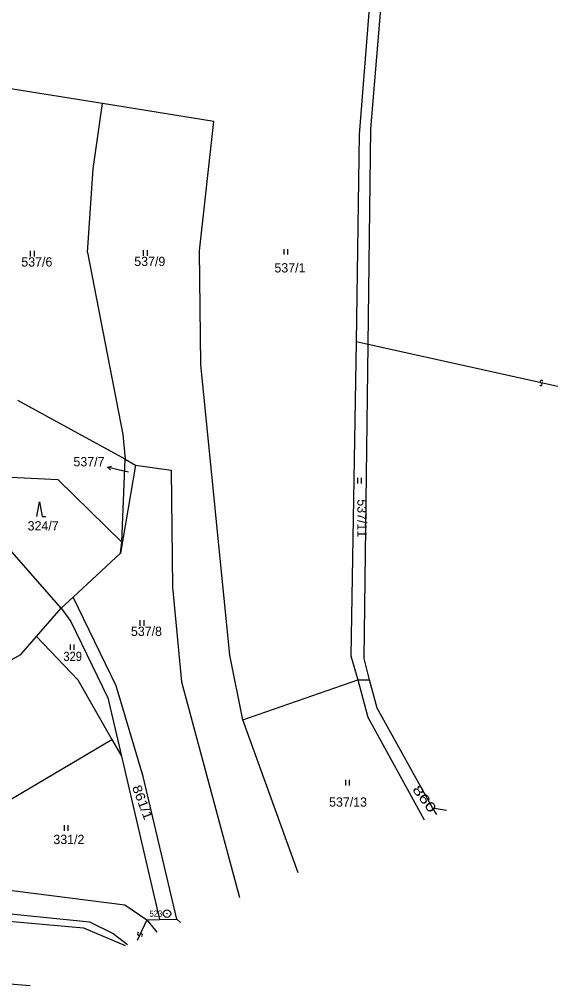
# Model space of a CAD drawing. Extents: x -680102 to -677253, y -1007548 to -1006096.
# Drawn here: x -679302.6 to -679159.4, y -1007457.9 to -1007197.5 of the extents above; entities that cross this region are included whole.
import ezdxf
from ezdxf.enums import TextEntityAlignment as Align

# ---------------------------------------------------------------- set-up
doc = ezdxf.new("R2010")
doc.units = 0
for name, color, linetype, lineweight in [('1', 7, 'Continuous', 25), ('16', 7, 'Continuous', 25), ('24', 7, 'Continuous', 25), ('25', 7, 'Continuous', 25), ('4', 7, 'Continuous', 25)]:
    doc.layers.add(name, color=color, linetype=linetype, lineweight=lineweight)
doc.layers.add('17', color=7, linetype='Continuous')
doc.layers.add('18', color=7, linetype='Continuous')

msp = doc.modelspace()

# ---------------------------------------------------------------- linework, layer by layer
at = {"layer": '1'}
for p, q in [((-679282.66, -1007237.83), (-679280.21, -1007220.22)), ((-679211, -1007228.57), (-679211.84, -1007284.41)), ((-679284.18, -1007260.33), (-679282.66, -1007237.83)), ((-679284.18, -1007260.33), (-679274.69, -1007309.38)), ((-679208.63, -1007285.12), (-679211.84, -1007284.41)), ((-679274.09, -1007316.01), (-679302.96, -1007300.22)), ((-679274.69, -1007309.38), (-679274.09, -1007316.01)), ((-679274.96, -1007338.38), (-679274.09, -1007316.01)), ((-679271.32, -1007317.64), (-679275.34, -1007341.36)), ((-679323.86, -1007319.92), (-679292.21, -1007321.54)), ((-679292.21, -1007321.54), (-679274.96, -1007338.38)), ((-679291.26, -1007356.13), (-679318.55, -1007325.27)), ((-679275.34, -1007341.36), (-679274.96, -1007338.38)), ((-679276.49, -1007377.07), (-679288.06, -1007353.16)), ((-679286.85, -1007375.44), (-679297.92, -1007363.78)), ((-679242.37, -1007386.23), (-679211.42, -1007375.5)), ((-679211.42, -1007375.5), (-679208.19, -1007375.44)), ((-679211.42, -1007375.5), (-679208.69, -1007385.51)), ((-679191.3, -1007409.95), (-679206.2, -1007383.07)), ((-679227.46, -1007427.46), (-679242.37, -1007386.23)), ((-679208.69, -1007385.51), (-679193.5, -1007413.16)), ((-679339.14, -1007427.85), (-679277.62, -1007391.57)), ((-679190.08, -1007411.72), (-679191.3, -1007409.95)), ((-679191.3, -1007409.95), (-679187.46, -1007410.62)), ((-679268.25, -1007440.13), (-679265.56, -1007443.49)), ((-679260.12, -1007439.93), (-679259.19, -1007440.81))]:
    msp.add_line(p, q, dxfattribs=at)
for points in [[(-679172.59, -1007083.3), (-679191.11, -1007116.05), (-679201.28, -1007152.6), (-679207.82, -1007187.68), (-679211, -1007228.57)], [(-679207.9, -1007227), (-679204.72, -1007189.29), (-679198.59, -1007153.11), (-679188.64, -1007117.51)], [(-679250.2, -1007225.05), (-679280.21, -1007220.22), (-679310.61, -1007215.32)], [(-679242.37, -1007386.23), (-679245.82, -1007368.82), (-679253.65, -1007290.55), (-679254.06, -1007259.86), (-679250.2, -1007225.05)], [(-679209.69, -1007369.72), (-679208.63, -1007285.12), (-679207.9, -1007227)], [(-679211.84, -1007284.41), (-679213.28, -1007369.02), (-679211.42, -1007375.5)], [(-679274.09, -1007316.01), (-679271.32, -1007317.64), (-679261.69, -1007318.94)], [(-679261.69, -1007318.94), (-679261.29, -1007350.54), (-679258.85, -1007375.99), (-679243.25, -1007434.1)], [(-679291.26, -1007356.13), (-679288.06, -1007353.16), (-679275.34, -1007341.36)], [(-679302.19, -1007368.68), (-679297.92, -1007363.78), (-679291.26, -1007356.13)], [(-679291.26, -1007356.13), (-679288.68, -1007359.78), (-679278.73, -1007380.32)], [(-679392.55, -1007422.66), (-679354.27, -1007397.43), (-679302.19, -1007368.68)], [(-679206.2, -1007383.07), (-679208.19, -1007375.44), (-679209.69, -1007369.72)], [(-679557.5, -1007373.16), (-679549.86, -1007376.28), (-679549.6, -1007376.39), (-679409.65, -1007424.66), (-679396.29, -1007429.27), (-679283.7, -1007440.7), (-679277.3, -1007443.79), (-679273.41, -1007446.8)], [(-679286.85, -1007375.44), (-679277.62, -1007391.57), (-679275.07, -1007396.04)], [(-679268.25, -1007440.13), (-679264.83, -1007440.05), (-679260.12, -1007439.93), (-679269.18, -1007401.47), (-679276.49, -1007377.07)], [(-679278.73, -1007380.32), (-679275.07, -1007396.04), (-679264.83, -1007440.05)], [(-679430.42, -1007423.5), (-679394.73, -1007432.51), (-679285.28, -1007442.24), (-679274.03, -1007447.06)], [(-679339.14, -1007427.85), (-679274.14, -1007436.07), (-679268.25, -1007440.13)], [(-679299.68, -1007457.86), (-679406.38, -1007449.32), (-679479.4, -1007434.83), (-679512.45, -1007434.27), (-679564.1, -1007436.71)]]:
    msp.add_lwpolyline(points, dxfattribs=at)
at = {"layer": '16'}
for p, q in [((-679275.91, -1007318.87), (-679278.824, -1007318.16)), ((-679273.15, -1007319.54), (-679275.91, -1007318.87))]:
    msp.add_line(p, q, dxfattribs=at)
msp.add_lwpolyline([(-679277.971, -1007318.882), (-679278.824, -1007318.16), (-679277.734, -1007317.911)], dxfattribs=at)
at = {"layer": '24'}
for radius in [1, 0.032]:
    msp.add_circle((-679262.78, -1007438.46), radius, dxfattribs=at)
at = {"layer": '25'}
for p, q in [((-679231.267, -1007260.915), (-679231.267, -1007259.415)), ((-679230.233, -1007260.915), (-679230.233, -1007259.415)), ((-679299.537, -1007261.395), (-679299.537, -1007259.895)), ((-679298.503, -1007261.395), (-679298.503, -1007259.895)), ((-679269.117, -1007261.255), (-679269.117, -1007259.755)), ((-679268.083, -1007261.255), (-679268.083, -1007259.755)), ((-679211.387, -1007322.585), (-679211.387, -1007321.085)), ((-679210.353, -1007322.585), (-679210.353, -1007321.085)), ((-679269.987, -1007360.905), (-679269.987, -1007359.405)), ((-679268.953, -1007360.905), (-679268.953, -1007359.405)), ((-679288.817, -1007367.425), (-679288.817, -1007365.925)), ((-679287.783, -1007367.425), (-679287.783, -1007365.925)), ((-679214.637, -1007403.945), (-679214.637, -1007402.445)), ((-679213.603, -1007403.945), (-679213.603, -1007402.445)), ((-679290.447, -1007416.125), (-679290.447, -1007414.625)), ((-679289.413, -1007416.125), (-679289.413, -1007414.625))]:
    msp.add_line(p, q, dxfattribs=at)
msp.add_lwpolyline([(-679297.89, -1007331.47), (-679297.14, -1007327.47), (-679296.39, -1007331.47), (-679295.39, -1007331.47)], dxfattribs=at)
for centre, radius, start, end in [((-679162.052, -1007295.848), 0.367, 204.68747, 77.09954), ((-679161.886, -1007295.131), 0.368, 24.68851, 256.61642), ((-679270.392, -1007443.901), 0.368, 102.37787, 334.23854), ((-679269.728, -1007444.218), 0.368, 281.74993, 154.55128)]:
    msp.add_arc(centre, radius, start, end, dxfattribs=at)
at = {"layer": '4'}
for p, q in [((-679115.31, -1007305.86), (-679208.63, -1007285.12)), ((-679268.25, -1007440.13), (-679270.83, -1007445.71))]:
    msp.add_line(p, q, dxfattribs=at)

# ---------------------------------------------------------------- texts
at = {"layer": '16'}
msp.add_text('537/7', height=2.5, dxfattribs=at).set_placement((-679279.63, -1007317.96), align=Align.RIGHT)
at = {"layer": '17', "width": 0.9}
msp.add_text('523', height=1.7, dxfattribs=at).set_placement((-679264.08, -1007439.31), align=Align.RIGHT)
at = {"layer": '18'}
for s, height, p in [('537/6', 2.5, (-679302.04, -1007264.13)), ('537/9', 2.5, (-679271.61, -1007263.99)), ('537/1', 2.5, (-679233.85, -1007265.72)), ('537/7', 0.1, (-679272.95, -1007319.34)), ('537/8', 2.5, (-679272.51, -1007363.64))]:
    msp.add_text(s, height=height, dxfattribs=at).set_placement(p)
msp.add_text('537/11', height=2.5, rotation=270.002, dxfattribs=at).set_placement((-679211.491, -1007326.83))
for s, p in [('324/7', (-679296.15, -1007335.23)), ('537/13', (-679214.02, -1007409.64)), ('331/2', (-679289.22, -1007419.71))]:
    msp.add_text(s, height=2.5, dxfattribs=at).set_placement(p, align=Align.CENTER)
at = {"layer": '18', "width": 0.9}
msp.add_text('329', height=2.5, dxfattribs=at).set_placement((-679288.199, -1007370.4), align=Align.CENTER)
at = {"layer": '18', "width": 1.15}
msp.add_text('861/1', height=2.5, rotation=290.502, dxfattribs=at).set_placement((-679270.559, -1007408.888), align=Align.CENTER)
at = {"layer": '18', "width": 1.45}
msp.add_text('860', height=2.5, rotation=306.902, dxfattribs=at).set_placement((-679196.84, -1007405.049))

doc.saveas('drawing.dxf')
